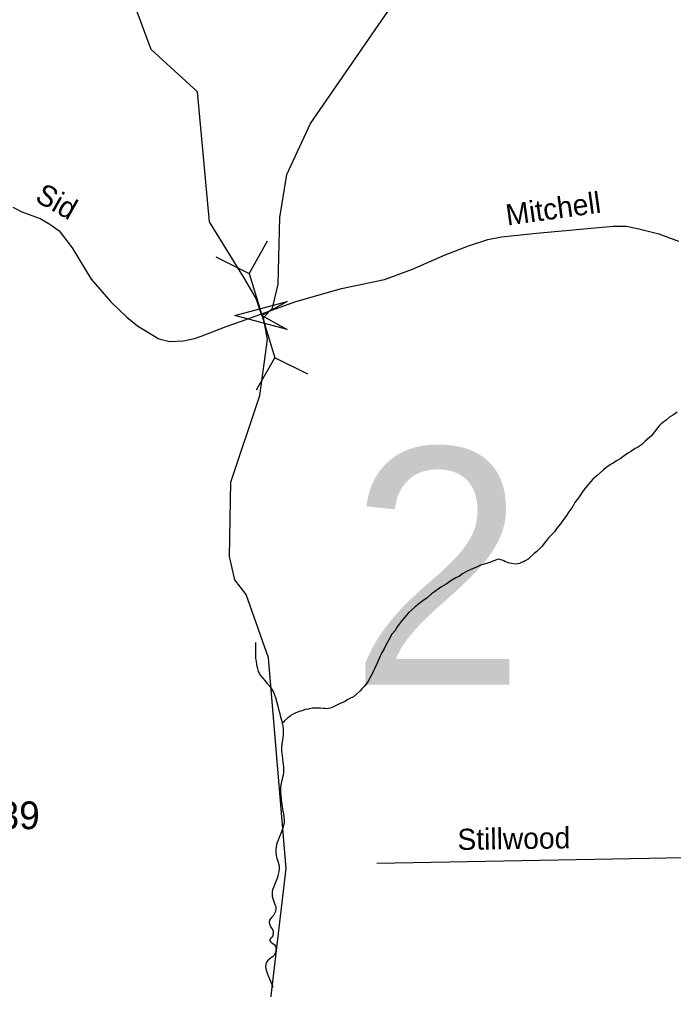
# Model space of a CAD drawing. Extents: x 2126262 to 2293712, y 749403 to 919119.
# Drawn here: x 2141263 to 2144211, y 828776 to 833147 of the extents above; entities that cross this region are included whole.
import ezdxf

# ---------------------------------------------------------------- set-up
doc = ezdxf.new("R2010")
doc.units = 0
for name, color, linetype in [('Exist Hydrographic Creek Single Shore', 7, 'Continuous'), ('Exist Hydrographic Misc Water Feature', 7, 'Continuous'), ('Exist Road Non-System Type 51', 7, 'Continuous'), ('Exist Road Non-System Type 51 Label', 7, 'Continuous'), ('Exist Road Secondary Structure Pipe Attributed CELL', 7, 'Continuous'), ('Exist Road Secondary Structure Pipe CELL', 7, 'Continuous'), ('Exist Road Secondary Structure Standard Bridge Number Label', 7, 'Continuous'), ('Exist Road Secondary Type 51 Attributed', 7, 'Continuous'), ('Exist Road Secondary Type 51 Label', 7, 'Continuous'), ('Exist Road Secondary Type 51 Number Label', 7, 'Continuous')]:
    doc.layers.add(name, color=color, linetype=linetype)

msp = doc.modelspace()

# ---------------------------------------------------------------- linework, layer by layer
at = {"layer": 'Exist Hydrographic Creek Single Shore'}
for points in [[(2142355.3, 831812.9), (2142329.7, 831890.1), (2142277.4, 831979.8), (2142118.5, 832235.7), (2142065.4, 832820.7), (2141856.5, 833012), (2141789.4, 833193.9), (2141479.6, 833659.6), (2141335.4, 834059.5), (2141359.4, 834259.2)], [(2140838.3, 825153.7), (2141380.6, 825709), (2141685.5, 826417.9), (2142008.4, 826972.3), (2142090.4, 827288.9), (2142096.6, 827705.4), (2142154.4, 827937.2), (2142236.8, 828089), (2142368.5, 828506.9), (2142464.5, 829321.8), (2142385.5, 830271.6), (2142284.4, 830555.8), (2142233.6, 830622.5), (2142208.6, 830728), (2142215.5, 831062.5), (2142346.5, 831453.4), (2142380.2, 831705.2), (2142362.5, 831804.2)]]:
    msp.add_lwpolyline(points, dxfattribs=at)
at = {"layer": 'Exist Hydrographic Misc Water Feature'}
for points in [[(2142362.5, 831804.2), (2142403.6, 831846), (2142428.6, 831953.7), (2142435.5, 832255.5), (2142467.5, 832448.3), (2142574.6, 832679), (2142996.6, 833290.4), (2143384.5, 834099.3), (2143739.5, 835017.2), (2143838.5, 835143.1), (2144037.4, 835319.5), (2144361.4, 835519.5), (2144519.5, 835663.9), (2144643.5, 835848.3), (2144851.4, 835949), (2144917.5, 836055.9), (2145016.5, 836332.7), (2145140.6, 836431.8), (2145229, 836472.8)], [(2144226.1, 831378.4), (2144210.6, 831366.1), (2144194.4, 831356), (2144176.7, 831341.6), (2144160.7, 831329.5), (2144155, 831325.5), (2144146.8, 831317.4), (2144138.8, 831307.6), (2144130.8, 831295.9), (2144123.2, 831287.7), (2144113, 831273), (2144101.3, 831263.4), (2144083.2, 831246.6), (2144065.6, 831230.7), (2144048, 831218.7), (2144037.5, 831214.6), (2144017.6, 831200.2), (2144007.8, 831194), (2143988.1, 831180.3), (2143970.2, 831167.6), (2143954, 831158.3), (2143938.5, 831148.1), (2143926.4, 831141.8), (2143914.3, 831133.5), (2143904.8, 831127.2), (2143894.8, 831117.8), (2143879, 831104.8), (2143866.7, 831092.8), (2143846.8, 831075.1), (2143829, 831055.1), (2143813.2, 831036.4), (2143803.3, 831022.9), (2143793.5, 831010.5), (2143781.6, 830992.1), (2143766, 830970.1), (2143756.2, 830952.5), (2143738.1, 830928), (2143724.6, 830907.8), (2143714.5, 830893.5), (2143700.8, 830874.1), (2143684.8, 830855.4), (2143673.3, 830839.3), (2143659.6, 830823.1), (2143647.3, 830811.2), (2143637.2, 830798.9), (2143625.6, 830785.2), (2143617.6, 830774.7), (2143610, 830764.9), (2143594.4, 830750.6), (2143582.1, 830740.3), (2143575.9, 830734.7), (2143562.4, 830722.5), (2143554.6, 830716), (2143542.3, 830708.2), (2143534.3, 830704.1), (2143528.6, 830702.1), (2143516.3, 830695.5), (2143508.9, 830694.1), (2143496.4, 830693.6), (2143480.6, 830695.6), (2143466.4, 830699.4), (2143450.2, 830705.1), (2143442.2, 830709.5), (2143432.6, 830713), (2143420.1, 830714.9), (2143380.3, 830701), (2143362.9, 830694.7), (2143340.5, 830688.8), (2143322.9, 830680.1), (2143304.6, 830672.3), (2143280.9, 830662.1), (2143258.7, 830649.2), (2143245.2, 830639.5), (2143229, 830631), (2143207, 830617.3), (2143185.1, 830603.1), (2143161.5, 830588.9), (2143149.6, 830580.9), (2143133.4, 830568.4), (2143120.1, 830558.6), (2143099.8, 830541.8), (2143080.1, 830528.2), (2143062.1, 830513.9), (2143044.2, 830499.5), (2143030.3, 830487.4), (2143014.5, 830471.5), (2142998.9, 830453.7)], [(2142998.9, 830453.7), (2142982.9, 830434.9), (2142964.9, 830410.9), (2142955.4, 830394.5), (2142941.5, 830376.8), (2142927.6, 830352.5), (2142915.9, 830330.7), (2142906, 830311.9), (2142894.3, 830292.6), (2142884.3, 830268.1), (2142872.6, 830243.9), (2142864.6, 830224.5), (2142857, 830209.7), (2142851.1, 830196.1), (2142843.1, 830182.3), (2142833.6, 830165.9), (2142825.4, 830152.1), (2142815.6, 830141.8), (2142805.3, 830131.2), (2142797.8, 830121.8), (2142781.8, 830107.2), (2142767.8, 830095.1), (2142752, 830087.3), (2142739.9, 830081), (2142730.1, 830074.4), (2142720.2, 830069), (2142707.9, 830064.4), (2142690.5, 830056.5), (2142678.4, 830050.2), (2142662.4, 830044.1), (2142654.6, 830042.4), (2142648.5, 830041.7), (2142640.9, 830042.1), (2142632.9, 830042.1), (2142618.3, 830044.3), (2142604.2, 830043.6), (2142596.6, 830043.5), (2142582.7, 830044), (2142568.5, 830041.7), (2142564.8, 830039.4), (2142550.9, 830037.4), (2142540.4, 830033.3), (2142530.8, 830031.1), (2142522.6, 830028.7), (2142512.7, 830024.9), (2142508.4, 830022.7), (2142498.8, 830018.5), (2142486.5, 830013.1), (2142482.8, 830008.4), (2142475, 830002.6), (2142470.9, 829998.8), (2142457, 829986.7), (2142453.1, 829980.4), (2142447.3, 829976.4)], [(2142325.9, 830339.6), (2142326.5, 830323.3), (2142326.1, 830301), (2142326.3, 830281.6), (2142327.2, 830268.1), (2142328.8, 830255.2), (2142330.6, 830241.1), (2142335.2, 830221.4), (2142339.1, 830209.9), (2142343.2, 830201.5), (2142349.3, 830191.7), (2142359.2, 830180), (2142367.8, 830169.8), (2142379.7, 830155.4), (2142387.9, 830145.7), (2142396.1, 830135.5), (2142405.5, 830119.1), (2142412.1, 830104.3), (2142415.9, 830092.7), (2142422.5, 830070.2), (2142426.8, 830052.9), (2142430.5, 830039), (2142434.4, 830024.2), (2142438.1, 830010.7), (2142440.6, 830000.1), (2142445.3, 829984.4), (2142447.3, 829976.4)], [(2142447.3, 829976.4), (2142449.2, 829964.8), (2142451.4, 829948.2), (2142451.6, 829926.3), (2142450, 829908.3), (2142445.9, 829884.5), (2142444, 829868.2), (2142444, 829849.9), (2142446.7, 829832.9), (2142448.3, 829814.8), (2142450.8, 829790.9), (2142452, 829778.5), (2142453.3, 829764.5), (2142452.7, 829753.7), (2142451.2, 829742.5), (2142447.1, 829726.1), (2142443.6, 829712), (2142439.3, 829689.1), (2142439.7, 829666.4), (2142440.6, 829650), (2142442.2, 829634.4), (2142444.2, 829618.6), (2142446.1, 829602.1), (2142448.6, 829588.3), (2142452.9, 829568.6), (2142454.7, 829554.6), (2142456.1, 829539.7), (2142456.1, 829529.2), (2142453.1, 829515.9), (2142449.4, 829504.6), (2142443.4, 829486.9), (2142437.7, 829471.9), (2142432.6, 829462.1), (2142428, 829449.9), (2142423.1, 829435.6), (2142420.1, 829419.8), (2142418, 829407.6), (2142418.2, 829393.7), (2142420.1, 829379.6), (2142422.5, 829368.3), (2142426.6, 829354.3), (2142430.9, 829340.3), (2142433, 829328.6), (2142432.8, 829320.5), (2142431.5, 829308.1), (2142429.1, 829295.9), (2142425.6, 829281.8), (2142422.5, 829273.8), (2142419.4, 829265.7), (2142415.7, 829255.7), (2142412.3, 829247.7), (2142407.3, 829236.3), (2142403.4, 829226), (2142401.6, 829217.7), (2142401.4, 829208), (2142402.2, 829197.8), (2142404.7, 829187.3), (2142408.2, 829178.2), (2142414.1, 829159.8), (2142417.4, 829150.9), (2142418.4, 829140.1), (2142416.4, 829127.8), (2142412.7, 829118.3), (2142407.5, 829110.1), (2142400.8, 829102.2), (2142393, 829094.1), (2142390.1, 829089.2), (2142388.7, 829078.5), (2142391.1, 829067.6), (2142396.3, 829057), (2142403.2, 829046.2), (2142405.9, 829039), (2142406.1, 829032.4), (2142405.1, 829024.1), (2142404.1, 829018.1), (2142400.2, 829012.7), (2142395.6, 829007.7), (2142391.8, 829002.1), (2142391.5, 828995.7), (2142396.1, 828989.7), (2142404.1, 828984), (2142411.8, 828978), (2142415.9, 828972.1), (2142418.6, 828964.8), (2142418.6, 828952.2), (2142415.9, 828941.7), (2142410.2, 828932), (2142402.4, 828923.9), (2142392.6, 828916), (2142381.9, 828907.9), (2142375.8, 828899.1), (2142372.7, 828891), (2142371.9, 828880.2), (2142373.1, 828869.9), (2142378.4, 828850.8), (2142382.9, 828837.5), (2142388.9, 828824.9), (2142394.6, 828813.4), (2142400.8, 828799.6), (2142404.3, 828786.8)]]:
    msp.add_lwpolyline(points, dxfattribs=at)
at = {"layer": 'Exist Road Non-System Type 51'}
msp.add_lwpolyline([(2144588.8, 829376.1), (2142873.2, 829344.2)], dxfattribs=at)
at = {"layer": 'Exist Road Secondary Structure Pipe Attributed CELL'}
msp.add_lwpolyline([(2142468.9, 831749.8), (2142233.3, 831812.9), (2142468.9, 831876), (2142355.3, 831812.9)], close=True, dxfattribs=at)
at = {"layer": 'Exist Road Secondary Structure Pipe CELL'}
for p, q in [((2142379.5, 832147.5), (2142297.3, 832002.6)), ((2142148.2, 832076.8), (2142297.3, 832002.6)), ((2142297.3, 832002.6), (2142413.2, 831623.2)), ((2142331, 831478.3), (2142413.2, 831623.2)), ((2142562.3, 831549), (2142413.2, 831623.2))]:
    msp.add_line(p, q, dxfattribs=at)
at = {"layer": 'Exist Road Secondary Type 51 Attributed'}
for points in [[(2141232.6, 832301.8), (2141272.9, 832280.5), (2141356.7, 832250.1), (2141400.1, 832224.6), (2141441.1, 832195), (2141500.6, 832118), (2141585.2, 831977), (2141674.5, 831874.2), (2141746, 831805.3), (2141795.1, 831766.4), (2141891.2, 831708.3), (2141941, 831696.2), (2142001.6, 831699.4), (2142051.4, 831710.2), (2142086.5, 831722.3), (2142194.6, 831763.8), (2142259.1, 831786.8), (2142345.9, 831818.1)], [(2142345.9, 831818.1), (2142507.7, 831876.1), (2142714.4, 831935.5), (2142908.5, 831974.8), (2143033.5, 832022.2), (2143180.8, 832087.2), (2143286.2, 832127.6), (2143373.7, 832155.7), (2143434.5, 832167.9), (2143592.9, 832183.7), (2143938.8, 832215.7), (2143996.2, 832215.7), (2144048.5, 832205.4), (2144143.9, 832180.6), (2144232.7, 832148)]]:
    msp.add_lwpolyline(points, dxfattribs=at)

# ---------------------------------------------------------------- texts
at = {"layer": 'Exist Road Non-System Type 51 Label'}
msp.add_text('Stillwood', height=95, rotation=0.8545, dxfattribs=at).set_placement((2143237.3, 829405.2))
at = {"layer": 'Exist Road Secondary Structure Standard Bridge Number Label'}
msp.add_text('2', height=1066.3, dxfattribs=at).set_placement((2142749.6, 830149.8))
at = {"layer": 'Exist Road Secondary Type 51 Label'}
for s, rotation, p in [('Sid', 330.5167, (2141327.8, 832331.2)), ('Mitchell', 7.9274, (2143461.2, 832218.1))]:
    msp.add_text(s, height=95, rotation=rotation, dxfattribs=at).set_placement(p)
at = {"layer": 'Exist Road Secondary Type 51 Number Label'}
msp.add_text('1139', height=125, dxfattribs=at).set_placement((2140982.5, 829498.9))

doc.saveas('drawing.dxf')
